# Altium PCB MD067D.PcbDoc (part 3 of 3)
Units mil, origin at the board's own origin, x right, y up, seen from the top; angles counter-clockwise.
Board outline 3650 x 4750 mil, 4 copper layers (Top Layer, GND Layer, Power Layer, Bottom Layer), stack 58.4 mil thick; 234 components, 118 nets, 588 pads, 975 vias.
Unrouted connection lines stored in the file: 45.
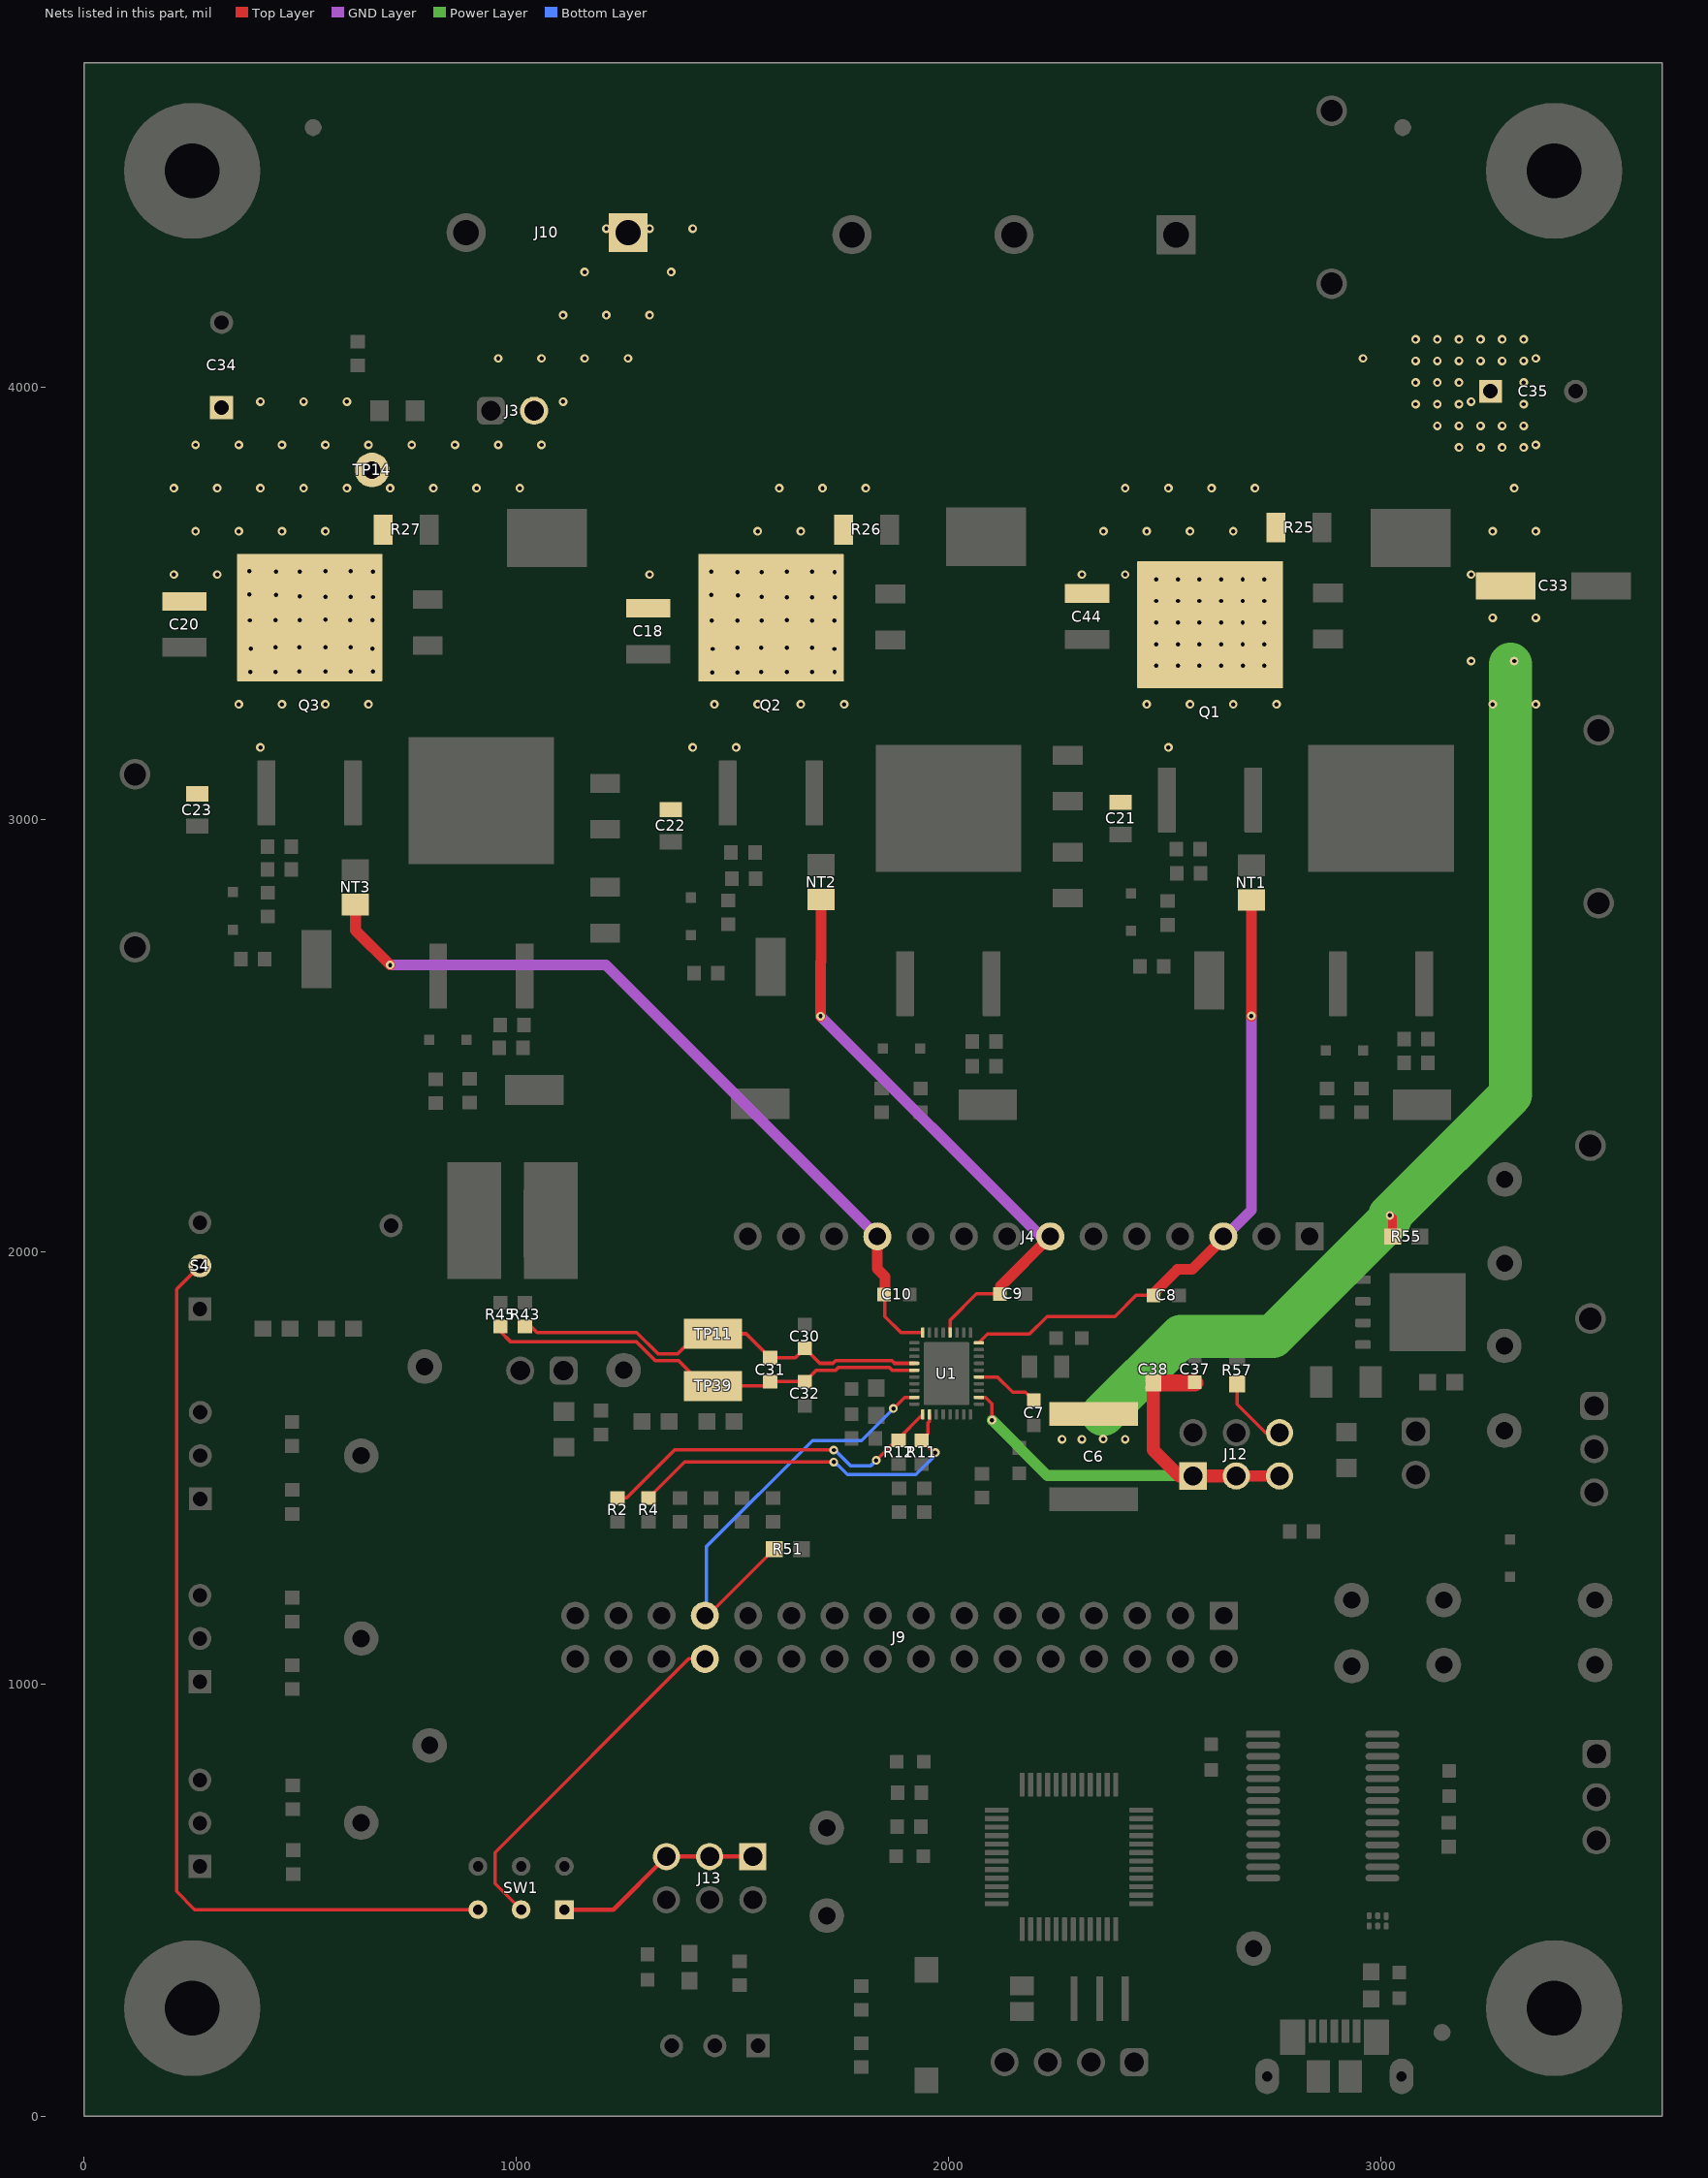
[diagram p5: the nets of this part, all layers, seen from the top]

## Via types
v1: diameter 20, hole 10, Top Layer to Bottom Layer, tented both sides, 899 vias
v2: diameter 20, hole 10, Top Layer to Bottom Layer, 67 vias
v3: diameter 19.68, hole 7.87, Top Layer to Bottom Layer, 8 vias
v4: diameter 20, hole 10, Top Layer to Bottom Layer, tented top, 1 vias

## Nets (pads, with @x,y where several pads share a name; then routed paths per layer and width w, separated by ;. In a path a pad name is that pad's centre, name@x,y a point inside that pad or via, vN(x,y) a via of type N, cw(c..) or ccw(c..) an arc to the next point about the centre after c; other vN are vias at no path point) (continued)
PVDD: C6.1 C7.2 C18.1 C20.1 C21.2 C22.2 C23.2 C33.1 C34.1 C35.1 C44.1 J3.2 J10.1 Q1.4 Q2.4 Q3.4 R25.1 R26.1 R27.1 R55.2 TP14.1 U1.5 | length 2451.3
  Top Layer w7.87: U1.5@2069.8,1710.13 2112.4,1710.13 2147.58,1674.94 2176.89,1674.94 C7.2@2197,1654.83
  Top Layer w20: v1(3020.14,2084) 3026.5,2077.64 R55.2@3026.5,2035
  Power Layer w100: 2357,1624 2536.77,1803.77 2749.43,1803.77 3020.14,2074.48 v1(3020.14,2084) 3299,2362.86 3299,3358.84
  other v1: 2261.89,1566 2308,1566 2357.15,1566.39 2408,1566 408,3166 1408,3166 1508,3166 2508,3166 358,3266 458,3266 558,3266 658,3266 1458,3266 1558,3266 1658,3266 1758,3266 2458,3266 2558,3266 2658,3266 2758,3266 3258,3266 3358,3266 2480,3355 2530,3355 2580,3355 2630,3355 2680,3355 2730,3355 3208,3366 3308,3366 2479.88,3404.96 2529.88,3404.96 2579.88,3404.96 2629.88,3404.96 2679.88,3404.96 2729.88,3404.96 2479.88,3454.96 2529.88,3454.96 2579.88,3454.96 2629.88,3454.96 2679.88,3454.96 2729.88,3454.96 3258,3466 3358,3466 2479.88,3504.96 2529.88,3504.96 2579.88,3504.96 2629.88,3504.96 2679.88,3504.96 2729.88,3504.96 2479.88,3554.96 2529.88,3554.96 2579.88,3554.96 2629.88,3554.96 2679.88,3554.96 2729.88,3554.96 208,3566 308,3566 1308,3566 2308,3566 2408,3566 3208,3566 258,3666 358,3666 458,3666 558,3666 1558,3666 1658,3666 2358,3666 2458,3666 2558,3666 2658,3666 3258,3666 3358,3666 208,3766 308,3766 408,3766 508,3766 608,3766 708,3766 808,3766 908,3766 1008,3766 1608,3766 1708,3766 1808,3766 2408,3766 2508,3766 2608,3766 2708,3766 3308,3766 3180,3860.14 3230,3860.14 3280,3860.14 3330,3860.14 258,3866 358,3866 458,3866 558,3866 658,3866 758,3866 858,3866 958,3866 1058,3866 3358,3866 3130,3910.14 3180,3910.14 3230,3910.14 3280,3910.14 3330,3910.14 3080,3960.14 3130,3960.14 3180,3960.14 3330,3960.14 408,3966 508,3966 608,3966 1108,3966 3208,3966 3080,4010.14 3130,4010.14 3180,4010.14 3330,4010.14 3080,4060.14 3130,4060.14 3180,4060.14 3230,4060.14 3280,4060.14 3330,4060.14 958,4066 1058,4066 1158,4066 1258,4066 2958,4066 3358,4066 3080,4110.14 3130,4110.14 3180,4110.14 3230,4110.14 3280,4110.14 3330,4110.14 1108,4166 1208,4166 1308,4166 1158,4266 1358,4266 1208,4366 1308,4366 1408,4366
  other v2: 1453,3340 1511.41,3340 385,3341 443.41,3341 1566,3341 1626,3341 1684.27,3341 1736,3341 498,3342 558,3342 616.27,3342 668,3342 1454,3394 1735.03,3394 386,3395 667.03,3395 1511.41,3396.6 1566,3397 1626,3396.6 1684.27,3397 443.41,3397.6 498,3398 558,3397.6 616.27,3398 1452,3459.15 384,3460.15 1511.41,3460 1567,3460 1683.84,3460 1735.03,3460 443.41,3461 499,3461 615.84,3461 667.03,3461 1626,3461 558,3462 1626,3513.17 1684.27,3513.17 1736.57,3513 558,3514.17 616.27,3514.17 668.57,3514 1567,3515 499,3516 1512,3518 444,3519 1450.66,3519 382.66,3520 1511.7,3572 1567,3572 1736,3572 443.7,3573 499,3573 668,3573 1450.66,3573 1626,3573 1684.27,3573 382.66,3574 558,3574 616.27,3574
SCL: R4.1 R11.2 U1.30 | length 848.4
  Top Layer w7.87: R4.1@1306,1430.36 1388.88,1513.24 1733.76,1513.24 v1(1734,1513) ; U1.30@1955.63,1623.51 1955.63,1607.96 1951.57,1603.9 1951.57,1578.13 R11.2@1937.29,1563.85 1937.29,1563.71 1967,1534 1968,1535 v1(1969,1535)
  Bottom Layer w7.87: v1(1734,1513) 1740.19,1506.81 1743.03,1506.81 1765.85,1484 1924,1484 1972,1532 v1(1969,1535)
SDA: R2.1 R12.2 U1.29 | length 818.1
  Top Layer w7.87: R2.1@1234,1430.36 1255.21,1430.36 1365.85,1541 v1(1734,1541) ; v1(1832,1517) 1878.85,1563.85 R12.2@1884.29,1563.85 1884.29,1567.92 U1.29@1939.88,1623.51
  Bottom Layer w7.87: v1(1734,1541) 1736.85,1541 1772.85,1505 1820,1505 v1(1832,1517)
SHA: C8.2 J4.3 NT1.1 U1.10 | length 1478.5
  Top Layer w7.87: U1.10@2069.8,1788.87 2089.98,1809.05 2186.59,1809.05 2227.54,1850 2384.38,1850 2433.38,1899 C8.2@2475.44,1899
  Top Layer w25: C8.2@2475.44,1899 2475.44,1905.18 2529.27,1959 2563,1959 J4.3@2634,2030 ; v1(2700,2545) NT1.1@2700,2813.5
  GND Layer w25: J4.3@2634,2030 2700,2096 v1(2700,2545)
SHB: C9.1 J4.7 NT2.1 U1.14 | length 1364.4
  Top Layer w7.87: U1.14@2002.87,1812.49 2002.87,1841.08 2063.92,1902.13 C9.1@2120,1902.13
  Top Layer w25: v1(1703.5,2544.5) 1703.5,2670 1704.76,2671.26 NT2.1@1704.76,2814.33 ; C9.1@2120,1902.13 2120,1920 J4.7@2235,2035
  GND Layer w25: v1(1703.5,2544.5) 2213,2035 J4.7@2235,2035
SHC: C10.1 J4.11 NT3.1 U1.18 | length 1855.3
  Top Layer w7.87: C10.1@1852.44,1901 1852.44,1849.56 1889.51,1812.49 U1.18@1939.88,1812.49
  Top Layer w25: NT3.1@627.77,2802.52 627.77,2743.23 v2(708,2663) ; J4.11@1835,2035 1835,1960 1852.44,1942.56 C10.1@1852.44,1901
  GND Layer w25: v2(708,2663) 1207,2663 J4.11@1835,2035
SN: C31.2 C32.1 R45.1 TP39.1 U1.23 | length 1041.7
  Top Layer w7.87: R45.1@963,1826.44 963,1815 986,1792 1276.73,1792 1320.47,1748.26 1374.41,1748.26 1433.67,1689 TP39.1@1454.87,1689 1576.56,1689 C31.2@1587,1699.44 1666.12,1699.44 C32.1@1667,1698.56 1694.31,1725.87 1739.02,1725.87 1744.88,1731.74 1862.61,1731.74 1868.47,1725.87 U1.23@1920.2,1725.87
SP: C30.2 C31.1 R43.1 TP11.1 U1.22 | length 996.4
  Top Layer w7.87: R43.1@1020,1826.44 1034.29,1826.44 1047.73,1813 1278,1813 1326.99,1764.01 1373.11,1764.01 1419.1,1810 TP11.1@1454.87,1810 1531.56,1810 C31.1@1587,1754.56 1645.12,1754.56 C30.2@1667,1776.44 1701.82,1741.62 1732.49,1741.62 1738.36,1747.49 1869.13,1747.49 1875,1741.62 U1.22@1920.2,1741.62
SPEED/WAKE: J9.25 R51.2 U1.27 | length 1013.2
  Top Layer w7.87: J9.25@1439,1161 J9.25@1436,1158 1442.5,1158 R51.2@1596.5,1312 ; v1(1872,1637) 1897.88,1662.88 U1.27@1920.2,1662.88
  Bottom Layer w7.87: J9.25@1436,1158 1439,1161 1439,1317 1685,1563 1798,1563 v1(1872,1637)
SPEED_IN: J13.1 J13.3 J13.5 SW1.1 | length 502.4
  Top Layer w10: SW1.1@1111,478 1224.21,478 J13.5@1347,600.79 J13.3@1447,600.79 ; J13.3@1436,611.79 J13.3@1447,600.79 ; J13.1@1547,600.79 J13.3@1447,600.79
SPEED_WAKE: J9.26 SW1.2 | length 827.6
  Top Layer w7.87: SW1.2@1011,478 951,538 951,610.36 1398.64,1058 J9.26@1436,1058
VREG: C37.2 C38.1 J12.1 J12.3 J12.5 U1.2 | length 1160.8
  Top Layer w7.87: U1.2@2069.8,1662.88 2085.35,1662.88 2100.19,1648.05 v1(2100.19,1610)
  Top Layer w25: J12.3@2665,1481 J12.5@2765,1481
  Top Layer w30: C38.1@2473,1696.11 2473,1541 2533,1481 J12.1@2565,1481 J12.3@2665,1481
  Top Layer w40: C38.1@2473,1696.11 C37.2@2569,1696.11
  Power Layer w25: v1(2100.19,1610) 2228.19,1482 2564,1482 J12.1@2565,1481
VREG_EXT_FET: J12.6 R57.2 | length 172.7
  Top Layer w7.87: R57.2@2667,1694.38 2667,1647 2733,1581 J12.6@2765,1581
WAKE: S4.2 SW1.3 | length 2183.8
  Top Layer w7.87: S4.2@268,1967 214,1913 214,520 256,478 SW1.3@911,478
pads on no net: FID1.1 FID2.1 FID3.1 H1.0 H2.0 H3.0 H4.0 H5.1 H6.1 H7.1 H8.1 J9.3 J9.4 J9.9 J9.10 J9.11 J9.13 J9.17 J9.19 Q7.9@3053.08,1802.91 Q7.9@3053.08,1860 Q7.9@3053.08,1917.09 Q7.9@3089.69,1860 Q7.9@3123.16,1802.91 Q7.9@3123.16,1860 Q7.9@3123.16,1917.09 SH-J1.0 SH-J2.0 SH-J3.0 SH-J4.0 SH-J5.0 SH-J6.0 SH-J7.0 SH-J8.0 SH-J10.0 SH-J11.0 SH-J12.0 SH-J13.0 SH-J14.0 SH-J15.0 SH-J16.0 SH-J17.0 SH-J18.0 SH-J19.0 SH-J20.0 SH-J21.0 SH-J22.0 SH-J23.0 SH-J24.0 U3.2 U3.3 U3.6 U3.8 U3.9 U3.10 U3.11 U3.12 U3.13 U3.14 U3.19 U3.22 U3.23 U3.24 U3.27 U3.28 U4.1 U5.3 U5.10 U5.11 U5.16 U5.17 U5.18 U5.19 U5.20 U5.21 U5.22 U5.25 U5.26 U5.30 U5.31 U5.32 U5.33 U5.34 U5.35 U5.36 U5.37 U5.38 U5.39 U5.40 U5.41 U5.45 U5.46 U5.47

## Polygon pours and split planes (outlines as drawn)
PVDD on Top Layer "TOP_LAYER_PVDD_P048" (solid, remove dead copper, pour order 48): 2176.39,1682.98 2447.09,1682.98 2447.09,1531.44 2230.06,1531.44 2176.39,1585.11
GND on Top Layer "TOP_LAYER_GND_P050" (solid, remove dead copper, pour order 50): 0,4750 3650,4750 3650,0 0,0
LSS on Top Layer "TOP_LAYER_LSS_P034" (solid, remove dead copper, pour order 34): 930,3000 3331.96,3000 3405,2926.96 3405,2741.26 3310,2646.26 3310,1970 1456.96,1967 1440.02,1936 1279.35,1936 1015.34,1936 1015.02,2015.84 1015.34,2205 903.27,2540 680.94,2705 680,2814.68 970,2931.8
PVDD on Top Layer "TOP_LAYER_PVDD_P008" (solid, remove dead copper, pour order 8): 710.13,3576.54 747.36,3613.77 747.36,3740.44 1015.44,3740.44 1450,4175 1450,4412.44 1412.44,4450 1174.2,4450 1124.2,4400 1124.2,4399.2 1100,4375 1100,4270 908,4078 613,4078 487.4,4000.4 301.85,3996.57 150.67,3845.39 150.67,3475 313.11,3475 313.11,3222.43 207.48,3155.59 207.48,3037.91 325.15,3037.91 653.18,3222.43 710.13,3279.38
OUTA on Top Layer "TOP_LAYER_OUTA_P006" (solid, remove dead copper, pour order 6): 2762.91,2853.5 2566,2853.5 2566,2952.97 2602.4,2989.37 2602.4,3215.17 2612.46,3225.23 2816.93,3225.23 2816.93,3461.89 2830.04,3475 2917.56,3475 2917.56,3715.16 2882.72,3750 2787.91,3750 2758.75,3788.66 2626.5,3788.66 2381.1,4059.1 2381.1,4450 2656.8,4450 2760.94,4345.85 2760.94,4184.69 3175,3770.63 3175,3252.2 3224.2,3203 3375,3203 3375,3125 3350,3100 3199.98,3100 3199.98,2804.88 3170.1,2775 2762.91,2775
OUTB on Top Layer "TOP_LAYER_OUTB_P004" (solid, remove dead copper, pour order 4): 1535,2840.23 1535,2862.2 1535,2937.94 1556.8,2947.42 1556.8,3189.49 1806.68,3189.49 1806.68,3448.8 1832.87,3475 1929.13,3475 1890.66,3800.2 1680,3800.2 1899.05,4025 1982.81,4108.76 1988.23,4450 2315,4450 2365,4450 2365,4058.16 2615.89,3790 2319.31,3790 2315,3726.04 2211.32,3622.36 2211.32,3219.5 2325,3219.5 2322.64,3217.14 2322.64,3089.49 2201.02,3089.49 2201.02,2833.6 2156.8,2789.37 1778.58,2789.37 1778.58,2853.5 1769.88,2862.2 1652,2862.2 1580.27,2862.2 1580.27,2840.23
OUTC on Top Layer "TOP_LAYER_OUTC_P002" (solid, remove dead copper, pour order 2): 465.1,3110.65 579.45,3225 747.36,3225 747.36,3439.57 736.93,3450 868.48,3450.2 868.48,3725 1006.9,3731.5 1745.5,4450 1960.31,4450 1964.76,4204.76 1964.76,4075 1690,3799.32 1575,3799.32 1410,3650 1275,3650 1200,3575 1200,3200 1265.99,3134.01 1265.99,3037.91 1137.91,3037.91 1121.97,3021.97 1121.97,2825 703.72,2825 683.31,2845.42 519.33,2845.42 465.1,2899.65
GLB_FET on Top Layer "TOP_LAYER_GLB_FET_P026" (solid, remove dead copper, pour order 26): 1903,2364.69 1904,2363.69 1903,2275.62 2175,2275.62 2175,2502.27 1975.47,2502.27 1926.42,2551.32 1926.42,2695.51 1919.81,2702.12 1868.41,2702.12 1868.31,2520 1903,2520
GHC_FET on Top Layer "TOP_LAYER_GHC_FET_P018" (solid, remove dead copper, pour order 18): 350,3135.78 350,2931.95 323.38,2905.33 323.38,2807.91 459.69,2807.91 467.6,2800 467.6,2650.51 500,2618.11 572.34,2618.11 572.34,2794.36 457.72,2908.98 457.72,3135.78
PVDD on Top Layer "TOP_LAYER_PVDD_P046" (solid, remove dead copper, pour order 46): 2890,4135 3356.77,4135 3375,4116.77 3375,3260.23 3345,3250.72 3150,3250.72 3150,3740 2890,4000
PVDD on Top Layer "TOP_LAYER_PVDD_P012" (solid, remove dead copper, pour order 12): 2803.49,3252.2 2803.49,3706.78 2725.26,3785 2291.73,3785 2291.73,3673.85 2244.09,3626.21 2235,3626.21 2235,3489.41 2250,3474.41 2422.56,3474.41 2435.08,3461.89 2435.08,3192.17 2350,3107.09 2350,3016.49 2360.98,3005.51 2437.68,3005.51 2450,3017.83 2450,3107.09 2564.4,3150 2592.91,3250 2602.4,3250
PVDD on Top Layer "TOP_LAYER_PVDD_P010" (solid, remove dead copper, pour order 10): 1775.57,3225 1775.57,3593.9 1806.68,3625 1803.68,3628 1801.38,3628 1801.38,3702.76 1848.62,3750 1893.74,3750 1892.29,3785 1489.15,3785 1341.24,3625 1287.6,3625 1225,3562.4 1225,3450.2 1400.43,3450.2 1411.06,3439.57 1411.06,3235.2 1411.06,3217.14 1382.58,3144.19 1300,3087.09 1300,2989.45 1425,2989.45 1559.71,3225
GND on Top Layer "TOP_LAYER_GND_P016" (solid, remove dead copper, pour order 16): 1169,3474.41 1434.08,3474.41 1437.58,3470.91 1437.58,3145.12 1173.88,3145.12 1169,3150
GND on Top Layer "TOP_LAYER_GND_P014" (solid, remove dead copper, pour order 14): 2184.35,3484.49 2443.8,3484.49 2462.2,3466.09 2462.2,3189.49 2459.53,3192.17 2184.35,3192.17
GLA_FET on Top Layer "TOP_LAYER_GLA_FET_P028" (solid, remove dead copper, pour order 28): 2875,2700 2922.73,2700 2927.73,2695 2935.94,2520 3060.5,2510 3060.5,2350 2920,2350 2915,2355 2915,2489.83 2875,2529.83
GLC_FET on Top Layer "TOP_LAYER_GLC_FET_P024" (solid, remove dead copper, pour order 24): 790,2715 855,2715 855,2560 907.42,2507.58 1024.72,2507.58 1024.72,2440.28 1085,2380 1080,2375 850,2375 850,2485.33 815,2520.33 790,2520.33
GHA_FET on Top Layer "TOP_LAYER_GHA_FET_P022" (solid, remove dead copper, pour order 22): 2445,3131.47 2575,3131.47 2575,2989 2546,2960 2546,2830.8 2635,2741.8 2635,2605 2564.4,2605 2564.4,2738.55 2522.95,2780 2409.59,2780 2409.59,2866.92 2445,2902.33
GHB_FET on Top Layer "TOP_LAYER_GHB_FET_P020" (solid, remove dead copper, pour order 20): 1445,3133.13 1447.66,3135.78 1565,3135.78 1565,2955 1522.44,2955 1522.44,2857.54 1625,2754.98 1625,2622.68 1617.32,2615 1533.11,2615 1530,2618.11 1530,2786.78 1526.78,2790 1380,2790 1380,2852.42 1445,2917.42
GND on Power Layer "POWER_LAYER_GND_P068" (solid, remove dead copper, pour order 72): 0,4750 3650,4750 3650,0 0,0
3V3_MCU on Power Layer "Power Layer-3V3_MCU" (solid, pour order 66): 3418,1593 2995,1170 2995,841 2996,840 2969,813 1824.2,813 1824.2,486.2 1668,330 1668,183 1671,186 2276,186 2276,60 2379,60 2379,454 1950,454 1950,735 2981,735 3089,843 3089,1097 3185,1097 3248,1160 3248,1289 3454,1495 3563,1495 3563,1593
PVDD on Power Layer "POWER_LAYER_PVDD_P062" (solid, remove dead copper, pour order 62): 1412.44,4450 1450,4412.44 1450,4198.1 1051.9,3800 3141,3800 2890,4091.68 2890,4135 3356.77,4135 3375,4116.77 3374,3800 3386,3788 3386,2845.5 3277.16,2736.66 416.21,2736.66 313.11,2839.76 313.11,3475 150.67,3475 150.67,3845.39 301.85,3996.57 561,3996.57 589.42,4025 855,4025 1100,4270 1100,4375.8 1174.2,4450
LSS on Power Layer "POWER_LAYER_LSS_P070" (solid, remove dead copper, pour order 70): 930,3000 3331.96,3000 3405,2926.96 3405,2741.26 3310,2646.26 3310,1970 3265,1925 1432.39,1922.04 1381,1828 1325,1828 1279.35,1936 1015.34,1936 1015.02,2015.84 1015.34,2205 903.27,2540 680.94,2705 680,2814.68 970,2931.8
OUTA on Power Layer "POWER_LAYER_OUTA_P058" (solid, remove dead copper, pour order 58): 3194,3755 2786.28,3755 2757.11,3793.66 2624.86,3793.66 2379.47,4064.1 2379.47,4455 2655.16,4455 2759.31,4350.85 2759.31,4189.69
OUTB on Power Layer "POWER_LAYER_OUTB_P056" (solid, remove dead copper, pour order 56): 2319,3800.2 1680,3800.2 1899.05,4025 1982.81,4108.76 1988.23,4450 2315,4450 2365,4450 2365,4058.16 2604,3800.2
OUTC on Power Layer "POWER_LAYER_OUTC_P054" (solid, remove dead copper, pour order 54): 1077.62,3801.84 1746.12,4451.84 1965.38,4450 1965.38,4206.6 1965.38,4076.84 1690.62,3801.16
PVDD on Power Layer "POWER_LAYER_PVDD_P052" (solid, remove dead copper, pour order 52): 2146,1700 2485,1700 2485,1554.34 2248.66,1554.34 2174.51,1628.49 2146,1628.49
5V_USB on Power Layer "POWER_LAYER_5V_USB_P060" (solid, pour order 60): 3100,452 3100,300 3099,299 3098,300 2611,300 2611,452 2614,452
AVDD on Power Layer "POWER_LAYER_AVDD_P068" (solid, remove dead copper, pour order 68): 1702.02,1474.76 1365.8,1474.76 1343,1451.96 1343,1347.29 1355.53,1334.76 1565,1334.76 1635,1400.31 1684.42,1400.31 1726.12,1442.01 1702.02,1466.11
GND on GND Layer "GND_LAYER_GND_P066" (solid, remove dead copper, pour order 82): 0,4750 3650,4750 3650,0 0,0
LSS on GND Layer "GND_LAYER_LSS_P080" (solid, remove dead copper, pour order 80): 930,3000 3331.96,3000 3405,2926.96 3405,2741.26 3310,2646.26 3310,1970 3265,1925 1432.39,1922.04 1381,1828 1325,1828 1279.35,1936 1015.34,1936 1015.02,2015.84 1015.34,2205 903.27,2540 680.94,2705 680,2814.68 970,2931.8
OUTA on GND Layer "GND_LAYER_OUTA_P078" (solid, remove dead copper, pour order 78): 3208.31,3754.48 2800.59,3754.48 2771.43,3793.14 2639.17,3793.14 2393.78,4063.58 2393.78,4454.48 2669.47,4454.48 2773.62,4350.33 2773.62,4189.17
OUTB on GND Layer "GND_LAYER_OUTB_P076" (solid, remove dead copper, pour order 76): 2319,3800.2 1680,3800.2 1899.05,4025 1982.81,4108.76 1988.23,4450 2315,4450 2365,4450 2365,4058.16 2604,3800.2
OUTC on GND Layer "GND_LAYER_OUTC_P074" (solid, remove dead copper, pour order 74): 1081.11,3801.82 1749.61,4451.82 1968.87,4449.99 1968.87,4206.59 1968.87,4076.82 1694.11,3801.15
GND on Bottom Layer "BOTTOM_LAYER_GND_P096" (solid, remove dead copper, pour order 96): -5.37,4724.31 3644.63,4724.31 3644.63,-25.69 -5.37,-25.69
LSS on Bottom Layer "BOTTOM_LAYER_LSS_P094" (solid, remove dead copper, pour order 94): 960,3071 3361.96,3071 3435,2997.96 3435,2812.26 3340,2717.26 3340,2041 3295,1996 1462.39,1993.04 1411,1899 1355,1899 1309.35,2007 1045.34,2007 1045.02,2086.84 1045.34,2276 933.27,2611 710.94,2776 710,2885.68 1000,3002.8
OUTA on Bottom Layer "BOTTOM_LAYER_OUTA_P088" (solid, remove dead copper, pour order 88): 3208.31,3750 2800.59,3750 2771.43,3788.66 2639.17,3788.66 2393.78,4059.1 2393.78,4450 2669.47,4450 2773.62,4345.85 2773.62,4184.69
OUTB on Bottom Layer "BOTTOM_LAYER_OUTB_P086" (solid, remove dead copper, pour order 86): 2325,3795 1686,3795 1905.06,4019.8 1988.81,4103.55 1994.23,4444.8 2321,4444.8 2371,4444.8 2371,4052.95 2610,3795
OUTC on Bottom Layer "BOTTOM_LAYER_OUTC_P084" (solid, remove dead copper, pour order 84): 1081.11,3801.82 1749.61,4451.82 1968.87,4449.99 1968.87,4206.59 1968.87,4076.82 1694.11,3801.15

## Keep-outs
Keep-Out Layer:
  text ".Layer_Name" at 577,-858.49 h60

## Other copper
Top Layer:
  pour cut-out: 906.09,2218 906.09,1838 979.71,1838 979.71,2218

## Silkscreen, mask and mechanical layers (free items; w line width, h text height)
Top Overlay:
  lines w8: 83.09,2227 390,2227 ; 86,2360 390,2360 ; 103,2269.5 115.5,2254.5 ; 103,2407 115.5,2422 ; 115.5,2309.5 115.5,2254.5 ; 115.5,2367 115.5,2422 ; 128,2269.5 115.5,2254.5 ; 128,2407 115.5,2422 ; 145.5,2167 145.5,2523 ; 210.5,2167 210.5,2525 ; 267.81,2168.82 268.05,2523 ; 329,2167 388,2167 390,2169 390,2526 ; 329.92,2526 390.08,2526 ; 1183,1349.2 1183,1521 1625,1521 ; 1183.2,1349 1627,1349 1627,1519 ; 83,2167 83,2526 328,2526 328,2167 83,2167
  text "30A Abs MAX" at 425,4292 h80
  text "PVDD" at 1215,4042 h30
  text "GND" at 850,4039 h30
  text "OUTA" at 2575,3962 h30 r90
  text "OUTC" at 1802,3961 h30 r90
  text "OUTB" at 2180,3958 h30 r90
  text "'.EVM_Orderable'" at 1794,3829 h120
  text "Rev 1.0" at 2239,3751 h80
  text "'.PRJ_Number'.PCB_Rev - '.EVM_Number'" at 116,3233 h108.27 r90
  text "ON" at 314,2414 h30 r90
  text "ACB" at 254,2398 h30 r90
  text "RUN" at 375,2391 h30 r90
  text "SLEEP" at 193,2373 h30 r90
  text "OFF" at 313,2248 h30 r90
  text "ABC" at 253,2246 h30 r90
  text "BRK" at 374,2243 h30 r90
  text "WAKE" at 194,2239 h30 r90
  text "Switches" at 65.5,2197 h30 r90
  text "1" at 371,2191 h30 r90
  text "S" at 128,2187 h30 r90
  text "3" at 250,2187 h30 r90
  text "4" at 192,2186 h30 r90
  text "2" at 312,2185 h30 r90
  text "LSS" at 1529.17,2102 h40 r45
  text "GLC" at 1623.17,2100 h40 r45
  text "SHC" at 1823.17,2097 h40 r45
  text "SHB" at 2230.44,2095 h40 r45
  text "BSTB" at 2330,2095 h40 r45
  text "GLA" at 2430,2095 h40 r45
  text "GHA" at 2536,2095 h40 r45
  text "BSTA" at 2732,2095 h40 r45
  text "GHC" at 1721.17,2094 h40 r45
  text "BSTC" at 1929.17,2094 h40 r45
  text "GLB" at 2042.17,2094 h40 r45
  text "GHB" at 2137.17,2094 h40 r45
  text "SHA" at 2629,2094 h40 r45
  text "GND" at 2854.17,2094 h40 r45
  text "3V3EXT" at 3260,1649 h30
  text "nFAULT" at 2866,1440 h30 r90
  text "3V3COM" at 3259,1428 h30
  text "HW Variant resistors" at 788,1365 h20
  text "DAC/SPEED" at 1817,1351 h22 r325
  text "SPD/WAKE" at 1326,1314 h22 r325
  text "nFAULT" at 2262,1302 h22 r325
  text "BRAKE" at 1268,1297 h22 r325
  text "DRVOFF" at 1060,1295 h22 r325
  text "FGOUT" at 2374,1291 h22 r325
  text "GND" at 2608,1266 h22 r325
  text "SDA" at 1594,1263 h22 r325
  text "SCL" at 1495.51,1261 h22 r325
  text "DIR" at 1202,1255 h22 r325
  text "NC" at 2509,1253 h22 r325
  text "NC" at 1706,1251 h22 r325
  text "NC" at 2112,1250 h22 r325
  text "NC" at 2209.1,1246 h22 r325
  text "NC" at 2010,1244 h22 r325
  text "NC" at 1812,1243 h22 r325
  text "NC" at 2525,941 h22 r45
  text "NC" at 2215,936 h22 r45
  text "GND" at 2615,927 h22 r45
  text "MSP_A1" at 2079,888 h22 r45
  text "MSP_A2" at 1983.13,887 h22 r45
  text "DIR_SW" at 1180,881 h22 r45
  text "MSP_STE" at 1759,862.99 h22 r45
  text "BRAKE_SW" at 1244,853 h22 r45
  text "DAC/SPEED" at 1843.49,844 h22 r45
  text "MSP_FGOUT" at 2353,840.95 h22 r45
  text "DRVOFF_SW" at 1057,839 h22 r45
  text "SPEED_WAKE" at 1332,834 h22 r45
  text "MSP_nFAULT" at 2248,829 h22 r45
  text "5V_EXT" at 3260,828 h30
  text "MSP_SOMI/SCL" at 1418,805 h22 r45
  text "MSP_SIMO/SDA" at 1511,796 h22 r45
  text "MSP_CLK_P4.5" at 1595,792 h22 r45
  text "5V_USB" at 3261,621 h30
  text "3.3V" at 2298,183 h25
  text "SBWTCK" at 2056,181 h25 r1.48
  text "GND" at 2405,43 h25
  text "SBWTDIO" at 2170.47,40 h25 r0.36
  text ".Layer_Name" at 577,-858.49 h60
Bottom Overlay:
  text ".Layer_Name" at 577,-858.49 h60
Top Paste:
  text ".Layer_Name" at 577,-858.49 h60
Bottom Paste:
  text ".Layer_Name" at 577,-858.49 h60
Top Solder:
  text ".Layer_Name" at 577,-858.49 h60
  text ".Layer_Name" at 577,-858.49 h60
Solder Side:
  text ".Layer_Name" at 577,-858.49 h60
Drill Guide:
  text ".Layer_Name" at 577,-858.49 h60
M1 Board Outline:
  the board outline again, w10
  text ".Layer_Name" at 577,-858.49 h60
M2 Board Dimensions:
  rectangle: 0,-275 125,-150
  rectangle: 125,-400 500,-275
  lines w7: 0,-275 1000,-275 ; 125,-400 125,-150 ; 250,-400 250,-150 ; 500,-400 500,-150 ; 750,-400 750,-150 ; 0,-400 1000,-400 1000,-150 0,-150 0,-400
  text ".Layer_Name" at 577,-858.49 h60
M3 3D STEP Top:
  text ".Layer_Name" at 577,-858.49 h60
M4 3D STEP Bottom:
  text ".Layer_Name" at 577,-858.49 h60
M5 Assembly Top:
  lines w10: -292,-930.17 6308,-930.17 ; -292,-726.83 6310,-726.83 ; -292,-523.5 -292,-1133.5 3713,-1133.5 6310,-1133.5 6310,-523.5 -291.5,-523.5 -291.5,-1133.5 1284,-1133.5 ; 2173,-1133.5 2173,-523.5 ; 3440,-726.83 3440,-523.5 ; 4280,-726.83 4280,-523.5 ; 4902,-1140 4902,-937.17
  text "COMPONENTS MARKED 'DNP' SHOULD NOT BE POPULATED." at 1153.5,-318.5 h60
  text "ASSEMBLY VARIANT:" at 1153,-434 h60
  text ".VariantName" at 2189,-434 h60
  text "PCB VIEWED FROM TOP SIDE" at -228.5,-655.67 h60
  text "BOARD #:" at 2248,-655.67 h60
  text ".PRJ_Number" at 2793.5,-655.67 h60
  text "REV:" at 3638,-655.67 h60
  text ".PCB_Rev" at 3929.5,-655.67 h60
  text "SVN REV:" at 4476,-655.67 h60
  text ".VersionControl_RevNumber" at 4982,-655.67 h60
  text "TID #:" at 2248,-859 h60
  text ".TID" at 2793.5,-859 h60
  text "PLOT NAME =" at -228.5,-1064.34 h60
  text ".plot_File_Name" at 577,-1064.34 h60
  text "GENERATED    :" at 2250,-1064.34 h60
  text ".Print_Date" at 3119.5,-1064.34 h60
  text ".Print_Time" at 3848.5,-1064.34 h60
  text "TEXAS INSTRUMENTS" at 5113,-1064.34 h60
M6 Assembly Bottom:
  lines w10: -292.5,-727.33 6309.5,-727.33 ; -290.5,-930.67 6309.5,-930.67 ; 1115.5,-1140.5 1115.5,-937.67 ; 1737.5,-727.33 1737.5,-524 ; 2577.5,-727.33 2577.5,-524 ; 3844.5,-1134 3844.5,-524 ; 4733.5,-1134 6309,-1134 6309,-524 -292.5,-524 -292.5,-1134 2304.5,-1134 6309.5,-1134 6309.5,-524
  text "COMPONENTS MARKED 'DNP' SHOULD NOT BE POPULATED." at 6102,-318 h60
  text ".VariantName" at 5058,-434 h60
  text "ASSEMBLY VARIANT:" at 6097,-434 h60
  text ".VersionControl_RevNumber" at 1035.5,-656.17 h60
  text "SVN REV:" at 1541.5,-656.17 h60
  text ".PCB_Rev" at 2088,-656.17 h60
  text "REV:" at 2379.5,-656.17 h60
  text ".PRJ_Number" at 3224,-656.17 h60
  text "BOARD #:" at 3769.5,-656.17 h60
  text "PCB VIEWED FROM BOTTOM SIDE" at 6246,-656.17 h60
  text ".TID" at 3224,-859.5 h60
  text "TID #:" at 3769.5,-859.5 h60
  text "TEXAS INSTRUMENTS" at 904.5,-1064.84 h60
  text ".Print_Time" at 2169,-1064.84 h60
  text ".Print_Date" at 2898,-1064.84 h60
  text "GENERATED    :" at 3767.5,-1064.84 h60
  text ".plot_File_Name" at 5440.5,-1064.84 h60
  text "PLOT NAME =" at 6246,-1064.84 h60
M9 Title Sheet:
  drawing of 57 lines, arcs and shapes, not listed
  text "1" at 739.84,8036.5 h70
  text "2" at 3235.5,8036.5 h70
  text "3" at 5724.84,8036.5 h70
  text "4" at 8231.51,8036.5 h70
  text "5" at 10730.5,8036.5 h70
  text "6" at 13235.5,8036.5 h70
  text "A" at -416.5,6893.5 h70
  text "A" at 14383.5,6893.5 h70
  text "B" at -416.5,4513.5 h70
  text "B" at 14383.5,4513.5 h70
  text "C" at -416.5,2138.5 h70
  text "C" at 14383.5,2138.5 h70
  text "PROJECT TITLE:" at 11343.5,277.5 h45
  text ".PRJ_Title" at 11393.5,144.17 h70
  text "DESIGNED FOR:" at 11343.5,-23.5 h45
  text ".PRJ_Customer" at 11393.5,-163.5 h70
  text "D" at -416.5,-231.5 h70
  text "D" at 14383.5,-231.5 h70
  text "FILE NAME:" at 11343.5,-323.5 h45
  text ".PCB_File_Name_No_Path" at 11393.5,-443.5 h70
  text "Texas Instruments (TI) and/or its licensors do not warrant the accuracy or completeness of this specification" at 6374,-605.34 h45
  text "ENGINEER:" at 11343.5,-613.5 h45
  text "LAYOUT BY:" at 12848.5,-613.5 h45
  text "or any information contained therein. TI and/or its licensors do not warrant that this design will meet" at 6329.01,-718 h45
  text ".PRJ_Engineer" at 11393.5,-768.49 h70
  text ".PCB_Layout" at 12899,-768.49 h70
  text "the specifications, will be suitable for your application or fit for any particular purpose, or will operate in" at 6329.01,-830.67 h45
  text ".Layer_Name" at 577,-858.49 h60
  text "ALTIUM DESIGNER VERSION:" at 12848.5,-923.5 h45
  text "an implementation. TI and/or its licensors do not warrant that the design is production worthy. You should" at 6329.01,-943.33 h45
  text "completely validate and test your design implementation to confirm the system functionality for your application." at 6374,-1056 h45
  text ".print_Scale" at 11393.5,-1056.83 h70
  text ".Application_BuildNumber" at 12899,-1056.83 h70
  text "1" at 739.84,-1263.5 h70
  text "2" at 3235.5,-1263.5 h70
  text "3" at 5724.84,-1263.5 h70
  text "4" at 8231.51,-1263.5 h70
  text "5" at 10730.5,-1263.5 h70
  text "6" at 13235.5,-1263.5 h70
M10 Fab Notes:
  drawing of 189 lines, arcs and shapes, not listed
  text "DESIGN INFORMATION" at 12382.02,6356.17 h60
  text "MIN. TRACK WIDTH:" at 11737.46,6224.05 h60
  text "8" at 12833.7,6224.05 h60
  text "MIL" at 12988.46,6224.05 h60
  text "MIN. CLEARANCE:" at 11737.46,6099.92 h60
  text "0.2" at 12773.7,6099.93 h60
  text "mm" at 12988.46,6099.92 h60
  text "MIN. VIA PAD SIZE:" at 11737.46,5975.8 h60
  text "30" at 12803.71,5975.8 h60
  text "MIL" at 12988.46,5975.8 h60
  text "0.05mm (2MIL)" at 12432.46,5845.9 h60
  text "MINIMUM ANNULAR RING" at 11408.23,5837.67 h60
  text "EXTERNAL" at 13140.46,5837.67 h60
  text "PER" at 11608.23,5727.55 h60
  text "IPC-D-275 CLASS 2 LEVEL C" at 11828.23,5727.54 h60
  text "MIL, HOLES" at 13316.46,5627.07 h60
  text "+/-" at 12924,5618.48 h60
  text "+/-" at 13778,5618.48 h60
  text "REGISTRATION TOLERANCES:" at 11408.23,5617.42 h60
  text "METAL" at 12608,5617.42 h60
  text "5" at 13184.2,5617.42 h60
  text "3" at 14017.2,5617.42 h60
  text "MIL" at 14133.46,5617.42 h60
  text "HOLE SIZE TOLERANCE (UNLESS OTHERWISE SPECIFIED):" at 11408.23,5519.1 h60
  text "+/-" at 13778,5516.23 h60
  text "3" at 14017.2,5515.17 h60
  text "MIL" at 14133.46,5515.17 h60
  text "MATERIAL:" at 11333.46,5377.52 h60
  text "FR-4 High Tg" at 12319.9,5249 h60
  text "X" at 12175.46,5241.01 h60
  text "FR-408" at 11754.46,5236.49 h60
  text "OTHER" at 13242.46,5236.49 h60
  text "62 MIL (1.6mm) +/-10%" at 12074.56,5093.46 h60
  text "X" at 11954.46,5091.01 h60
  text "THICKNESS:" at 11408.23,5085.24 h60
  text "OTHER" at 13359.46,5085.24 h60
  text "TOLERANCE:" at 11408.23,4946.92 h60
  text "X" at 12256.46,4946.92 h60
  text "ANSI IPC-6012 TYPE 3 CLASS 2" at 12434.48,4946.92 h60
  text "OTHER +/-" at 12434.46,4802.73 h60
  text "BOW & TWIST:" at 11408.23,4657.54 h60
  text "X" at 12256.46,4657.54 h60
  text "ANSI IPC-6012 TYPE 3 CLASS 2" at 12434.48,4657.54 h60
  text "OTHER +/-" at 12434.46,4510.85 h60
  text "DRILLING:" at 11333.46,4380.23 h60
  text "NC_DRILL FILES" at 13094.46,4275.04 h60
  text "REFERENCE:" at 11408.23,4271.1 h60
  text "X" at 12065.46,4271.01 h60
  text "AS SHOWN" at 12243.46,4271.1 h60
  text "X" at 12966.46,4271.1 h60
  text "OTHER" at 13392.46,4128.85 h60
  text "PTH COPPER THICKNESS:" at 11407.91,4125.32 h60
  text "X" at 12547.14,4125.32 h60
  text "20-30 um" at 12675.14,4125.32 h60
  text "BOARD FINISH:" at 11333.46,3977.73 h60
  text "SILKSCREEN:" at 11488.68,3867.6 h60
  text "X" at 12446.46,3867.6 h60
  text "TOP" at 12563.46,3867.6 h60
  text "X" at 12956.46,3867.6 h60
  text "BOTTOM" at 13074.46,3867.6 h60
  text "SILKSCREEN COLOR:" at 11488.68,3712.41 h60
  text "X" at 12445.46,3712.41 h60
  text "WHITE" at 12563.46,3712.41 h60
  text "OTHER" at 13074.46,3712.41 h60
  text "X" at 12576.46,3568.96 h60
  text "GREEN" at 12694.46,3568.96 h60
  text "OTHER" at 13312.46,3568.96 h60
  text "SOLDER RESIST COLOR:" at 11488.68,3562.1 h60
  text "X" at 12576.46,3414.71 h60
  text "MATTE" at 12694.46,3414.71 h60
  text "SEMI-GLOSS" at 13312,3414.07 h60
  text "IMMERSION GOLD (ENIG)" at 12394.46,3241.94 h60
  text "ENEPIG" at 13732,3234.72 h60
  text "SURFACE FINISH:" at 11333.46,3233.72 h60
  text "X" at 12216.46,3233.72 h60
  text "IMM. TIN/SILVER OR EQUIV" at 11663,3096.4 h60
  text "OTHER" at 13094.46,3092.47 h60
  text "ARRAY/PANEL:" at 11333.46,2937.09 h60
  text "CUT AND TRIM PER M1 BOARD OUTLINE" at 12394.46,2928.87 h60
  text "N.C. ROUTE" at 12394.46,2792.9 h60
  text "X" at 13082.46,2792.9 h60
  text "V. SCORE" at 13260.46,2792.9 h60
  text "CERTIFICATION:" at 11333.46,2663.77 h60
  text "MATERIALS AND WORKMANSHIP FOR ALL PCBS" at 12058.46,2663.77 h60
  text "TO MEET OR EXCEED THE REQUIREMENTS OF:" at 12058.46,2569.71 h60
  text "X" at 11695.97,2441.08 h60
  text "ANSI IPC-A-600F CLASS ->" at 11823.96,2441.08 h60
  text "X" at 13471.97,2441.08 h60
  text "2" at 13581.96,2441.08 h60
  text "1" at 13266.96,2439.58 h60
  text "3" at 13935.96,2439.58 h60
  text "X" at 12507.97,2293.39 h60
  text "RoHS" at 12635.96,2293.39 h60
  text "OTHER" at 13280.36,2293.39 h60
  text "PER ORDER" at 13677.42,2293.39 h60
  text "ALL BOARDS MUST MEET OR EXCEED UL94-V0 REQUIREMENTS." at 11361,2139.57 h60
  text "PCB MUST BEAR THE UL94V-0 UL REGISTERED MATERIAL ID NUMBER" at 11361,2023.5 h60
  text "ADDITIONAL REQUIREMENTS:" at 11333.46,1854.08 h60
  text "MICROSECTION:" at 11408.23,1746.95 h60
  text "YES" at 12313.96,1746.95 h60
  text "REQUIRED" at 13175.46,1602.62 h60
  text "BARE BOARD ELEC. TEST:" at 11408.23,1599.76 h60
  text "NONE" at 12713.96,1599.76 h60
  text "X" at 13057.46,1599.76 h60
  text "PER ORDER" at 13767.46,1599.76 h60
  text "XX MIL VIAS REQUIRE NON-CONDUCTIVE FILL AND PLANARIZE" at 11576.38,1394.82 h59
  text "XX MIL VIAS REQUIRE CONDUCTIVE FILL AND PLANARIZE" at 11584.38,1290.84 h60
  text "OUTER XX MIL TRACES REQUIRE 50 OHM SINGLE-ENDED IMPEDANCE" at 11583.39,1127.46 h58
  text "LAYER 2 & 3 (INNER LAYERS) XX MIL WIDE, XX MIL SPACE / TRACES REQUIRE 100 OHM DIFFERENTIAL IMPEDANCE" at 11575.39,891.74 h60
  text ".Layer_Name" at 577,-858.49 h60
M11 Gerber Information:
  lines w10: -292,-930.17 6308,-930.17 ; -292,-726.83 6310,-726.83 ; -292,-523.5 -292,-1133.5 3713,-1133.5 6310,-1133.5 6310,-523.5 -291.5,-523.5 -291.5,-1133.5 1284,-1133.5 ; 2173,-1133.5 2173,-523.5 ; 3440,-726.83 3440,-523.5 ; 4280,-726.83 4280,-523.5 ; 4902,-1140 4902,-937.17
  text "ALL ARTWORK VIEWED FROM TOP SIDE" at -228.5,-655.67 h60
  text "BOARD #:" at 2248,-655.67 h60
  text ".PRJ_Number" at 2793.5,-655.67 h60
  text "REV:" at 3638,-655.67 h60
  text ".PCB_Rev" at 3929.5,-655.67 h60
  text "SVN REV:" at 4476,-655.67 h60
  text ".VersionControl_RevNumber" at 4982,-655.67 h60
  text "LAYER NAME =" at -228.5,-858.49 h60
  text "TID #:" at 2248,-859 h60
  text ".TID" at 2793.5,-859 h60
  text "PLOT NAME =" at -228.5,-1064.34 h60
  text ".plot_File_Name" at 577,-1064.34 h60
  text "GENERATED    :" at 2250,-1064.34 h60
  text ".Print_Date" at 3119.5,-1064.34 h60
  text ".Print_Time" at 3848.5,-1064.34 h60
  text "TEXAS INSTRUMENTS" at 5113,-1064.34 h60
M12 Stackup:
  drawing of 295 lines, arcs and shapes, not listed
  text "Layer" at 6519.09,7161 h60
  text "Name" at 6929,7161 h60
  text "Material" at 7858.74,7161 h60
  text "Thickness" at 8718.51,7161 h60
  text "Constant" at 9368.35,7161 h60
  text "Board Layer Stack" at 9938.21,7161 h60
  text "Top Overlay" at 6929,7041 h60
  text "Top Solder" at 6929,6921 h60
  text "Solder Resist" at 7858.74,6921 h60
  text "0.40mil" at 8718.51,6921 h60
  text "3.5" at 9368.35,6921 h60
  text "1" at 6519.09,6801 h60
  text "Top Layer" at 6929,6801 h60
  text "2.80mil" at 8718.51,6801 h60
  text "Dielectric 2" at 6929,6681 h60
  text "FR-4" at 7858.74,6681 h60
  text "10.00mil" at 8718.51,6681 h60
  text "4.8" at 9368.35,6681 h60
  text "2" at 6519.09,6561 h60
  text "GND Layer" at 6929,6561 h60
  text "1.40mil" at 8718.51,6561 h60
  text "Dielectric 1" at 6929,6441 h60
  text "FR-4" at 7858.74,6441 h60
  text "30.00mil" at 8718.51,6441 h60
  text "4.2" at 9368.35,6441 h60
  text "3" at 6519.09,6321 h60
  text "Power Layer" at 6929,6321 h60
  text "1.40mil" at 8718.51,6321 h60
  text "Dielectric 3" at 6929,6201 h60
  text "FR-4" at 7858.74,6201 h60
  text "10.00mil" at 8718.51,6201 h60
  text "4.8" at 9368.35,6201 h60
  text "4" at 6519.09,6081 h60
  text "Bottom Layer" at 6929,6081 h60
  text "2.80mil" at 8718.51,6081 h60
  text "Solder Side" at 6929,5961 h60
  text "Solder Resist" at 7858.74,5961 h60
  text "0.40mil" at 8718.51,5961 h60
  text "3.5" at 9368.35,5961 h60
  text "Bottom Overlay" at 6929,5841 h60
  text ".Layer_Name" at 577,-858.49 h60
M13 Component Bodies Top:
  text ".Layer_Name" at 577,-858.49 h60
M14 Component Bodies Bottom:
  text ".Layer_Name" at 577,-858.49 h60
M15 Courtyards Top:
  text ".Layer_Name" at 577,-858.49 h60
M16 Courtyards Bottom:
  text ".Layer_Name" at 577,-858.49 h60
Drill Drawing:
  circle w10: c5363.72,3459.18 r16.58
  circle w10: c5363.72,3459.18 r27.63
  circle w10: c5363.72,2464.62 r27.63
  lines w10: 5336.09,2312.67 5336.09,2326.49 5349.9,2340.3 5336.09,2354.11 5336.09,2367.93 5349.9,2367.93 5363.72,2354.11 5377.53,2367.93 5391.34,2367.93 5391.34,2354.11 5377.53,2340.3 5391.34,2326.49 5391.34,2312.67 5377.53,2312.67 5363.72,2326.49 5349.9,2312.67 5336.09,2312.67 ; 5336.09,2575.13 5349.9,2575.13 5363.72,2561.31 5377.53,2575.13 5391.34,2575.13 5377.53,2588.94 5391.34,2602.75 5377.53,2602.75 5363.72,2616.57 5349.9,2602.75 5336.09,2602.75 5349.9,2588.94 5336.09,2575.13 ; 5336.09,2740.89 5391.34,2740.89 5363.72,2685.63 5336.09,2740.89 ; 5336.09,2823.77 5349.9,2823.77 5349.9,2809.95 5377.53,2809.95 5377.53,2823.77 5391.34,2823.77 5391.34,2851.39 5377.53,2851.39 5377.53,2865.21 5349.9,2865.21 5349.9,2851.39 5336.09,2851.39 5336.09,2823.77 ; 5336.09,2934.27 5363.72,2948.09 5391.34,2934.27 5377.53,2961.9 5391.34,2989.53 5363.72,2975.71 5336.09,2989.53 5349.9,2961.9 5336.09,2934.27 ; 5336.09,3072.41 5349.9,3072.41 5363.72,3058.59 5377.53,3072.41 5391.34,3072.41 5377.53,3086.22 5391.34,3100.03 5377.53,3100.03 5363.72,3113.85 5349.9,3100.03 5336.09,3100.03 5349.9,3086.22 5336.09,3072.41 ; 5336.09,3210.54 5363.72,3182.91 5391.34,3210.54 5363.72,3238.17 5336.09,3210.54 ; 5336.09,3307.23 5391.34,3307.23 5391.34,3362.49 5336.09,3362.49 5336.09,3307.23 ; 5336.09,3611.13 5391.34,3611.13 5363.72,3555.87 5336.09,3611.13 ; 5347.14,2580.65 5355.43,2580.65 5363.72,2572.36 5372.01,2580.65 5380.29,2580.65 5372.01,2588.94 5380.29,2597.23 5372.01,2597.23 5363.72,2605.52 5355.43,2597.23 5347.14,2597.23 5355.43,2588.94 5347.14,2580.65 ; 5347.14,3600.08 5380.29,3600.08 5363.72,3566.93 5347.14,3600.08
  lines w12: 5286,2275.38 8517.49,2275.38 ; 5286,3642.9 8517.49,3642.9 ; 5623.86,2151.06 5623.86,3767.22 ; 5955.86,2151.06 5955.86,3767.22 ; 6592.43,2151.06 6592.43,3767.22 ; 6851.57,2151.06 6851.57,3767.22 ; 7226.72,2151.06 7226.72,3767.22 ; 7951.05,2151.06 7951.05,3767.22 ; 5286,2151.06 8517.49,2151.06 8517.49,3767.22 5286,3767.22 5286,2151.06
  text "Symbol" at 5360.59,3680.19 h72
  text "Quantity" at 5661.16,3680.19 h72
  text "Finished Hole Size" at 5993.16,3680.19 h72
  text "Plated" at 6629.72,3680.19 h72
  text "Hole Type" at 6888.86,3680.19 h72
  text "Drill Layer Pair" at 7264.02,3680.19 h72
  text "Hole Tolerance" at 7988.35,3680.19 h72
  text "8" at 5661.16,3555.87 h60
  text "7.87mil (0.200mm)" at 5993.16,3555.87 h60
  text "PTH" at 6629.72,3555.87 h60
  text "Round" at 6888.86,3555.87 h60
  text "Top Layer - Bottom Layer" at 7264.02,3555.87 h60
  text "964" at 5661.16,3431.55 h60
  text "10.00mil (0.254mm)" at 5993.16,3431.55 h60
  text "PTH" at 6629.72,3431.55 h60
  text "Round" at 6888.86,3431.55 h60
  text "Top Layer - Bottom Layer" at 7264.02,3431.55 h60
  text "6" at 5661.16,3307.23 h60
  text "23.62mil (0.600mm)" at 5993.16,3307.23 h60
  text "PTH" at 6629.72,3307.23 h60
  text "Round" at 6888.86,3307.23 h60
  text "Top Layer - Bottom Layer" at 7264.02,3307.23 h60
  text "20" at 5661.16,3182.91 h60
  text "33.47mil (0.850mm)" at 5993.16,3182.91 h60
  text "PTH" at 6629.72,3182.91 h60
  text "Round" at 6888.86,3182.91 h60
  text "Top Layer - Bottom Layer" at 7264.02,3182.91 h60
  text "66" at 5661.16,3058.59 h60
  text "40.00mil (1.016mm)" at 5993.16,3058.59 h60
  text "PTH" at 6629.72,3058.59 h60
  text "Round" at 6888.86,3058.59 h60
  text "Top Layer - Bottom Layer" at 7264.02,3058.59 h60
  text "12" at 5661.16,2934.27 h60
  text "43.31mil (1.100mm)" at 5993.16,2934.27 h60
  text "PTH" at 6629.72,2934.27 h60
  text "Round" at 6888.86,2934.27 h60
  text "Top Layer - Bottom Layer" at 7264.02,2934.27 h60
  text "16" at 5661.16,2809.95 h60
  text "45.28mil (1.150mm)" at 5993.16,2809.95 h60
  text "PTH" at 6629.72,2809.95 h60
  text "Round" at 6888.86,2809.95 h60
  text "Top Layer - Bottom Layer" at 7264.02,2809.95 h60
  text "8" at 5661.16,2685.63 h60
  text "51.18mil (1.300mm)" at 5993.16,2685.63 h60
  text "PTH" at 6629.72,2685.63 h60
  text "Round" at 6888.86,2685.63 h60
  text "Top Layer - Bottom Layer" at 7264.02,2685.63 h60
  text "5" at 5661.16,2561.31 h60
  text "59.06mil (1.500mm)" at 5993.16,2561.31 h60
  text "PTH" at 6629.72,2561.31 h60
  text "Round" at 6888.86,2561.31 h60
  text "Top Layer - Bottom Layer" at 7264.02,2561.31 h60
  text "4" at 5661.16,2436.99 h60
  text "125.98mil (3.200mm)" at 5993.16,2436.99 h60
  text "PTH" at 6629.72,2436.99 h60
  text "Round" at 6888.86,2436.99 h60
  text "Top Layer - Bottom Layer" at 7264.02,2436.99 h60
  text "2" at 5661.16,2312.67 h60
  text "23.62mil (0.600mm)" at 5993.16,2312.67 h60
  text "PTH" at 6629.72,2312.67 h60
  text "Slot" at 6888.86,2312.67 h60
  text "Top Layer - Bottom Layer" at 7264.02,2312.67 h60
  text "1111 Total" at 5661.16,2188.35 h60
  text "Slot definitions :" at 5360.59,2101.33 h60
  text "Routed Path Length" at 5811.31,2101.33 h60
  text "= Calculated from tool start centre position to tool end centre position." at 6351.05,2101.33 h60
  text "Hole Length" at 5811.31,2051.6 h60
  text "= Routed Path Length + Tool Size = Slot length as defined in the PCB layout" at 6151.24,2051.6 h60
  text ".Layer_Name" at 577,-858.49 h60
M17 Embedded Cavity:
  text ".Layer_Name" at 577,-858.49 h60
M18 Embedded Assembly:
  text ".Layer_Name" at 577,-858.49 h60
M19 Embedded Keepout:
  text ".Layer_Name" at 577,-858.49 h60

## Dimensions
0,-400 to 1000,-400 on M2 Board Dimensions
0,0 to 0,4750 on M2 Board Dimensions
0,0 to 3650,0 on M2 Board Dimensions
